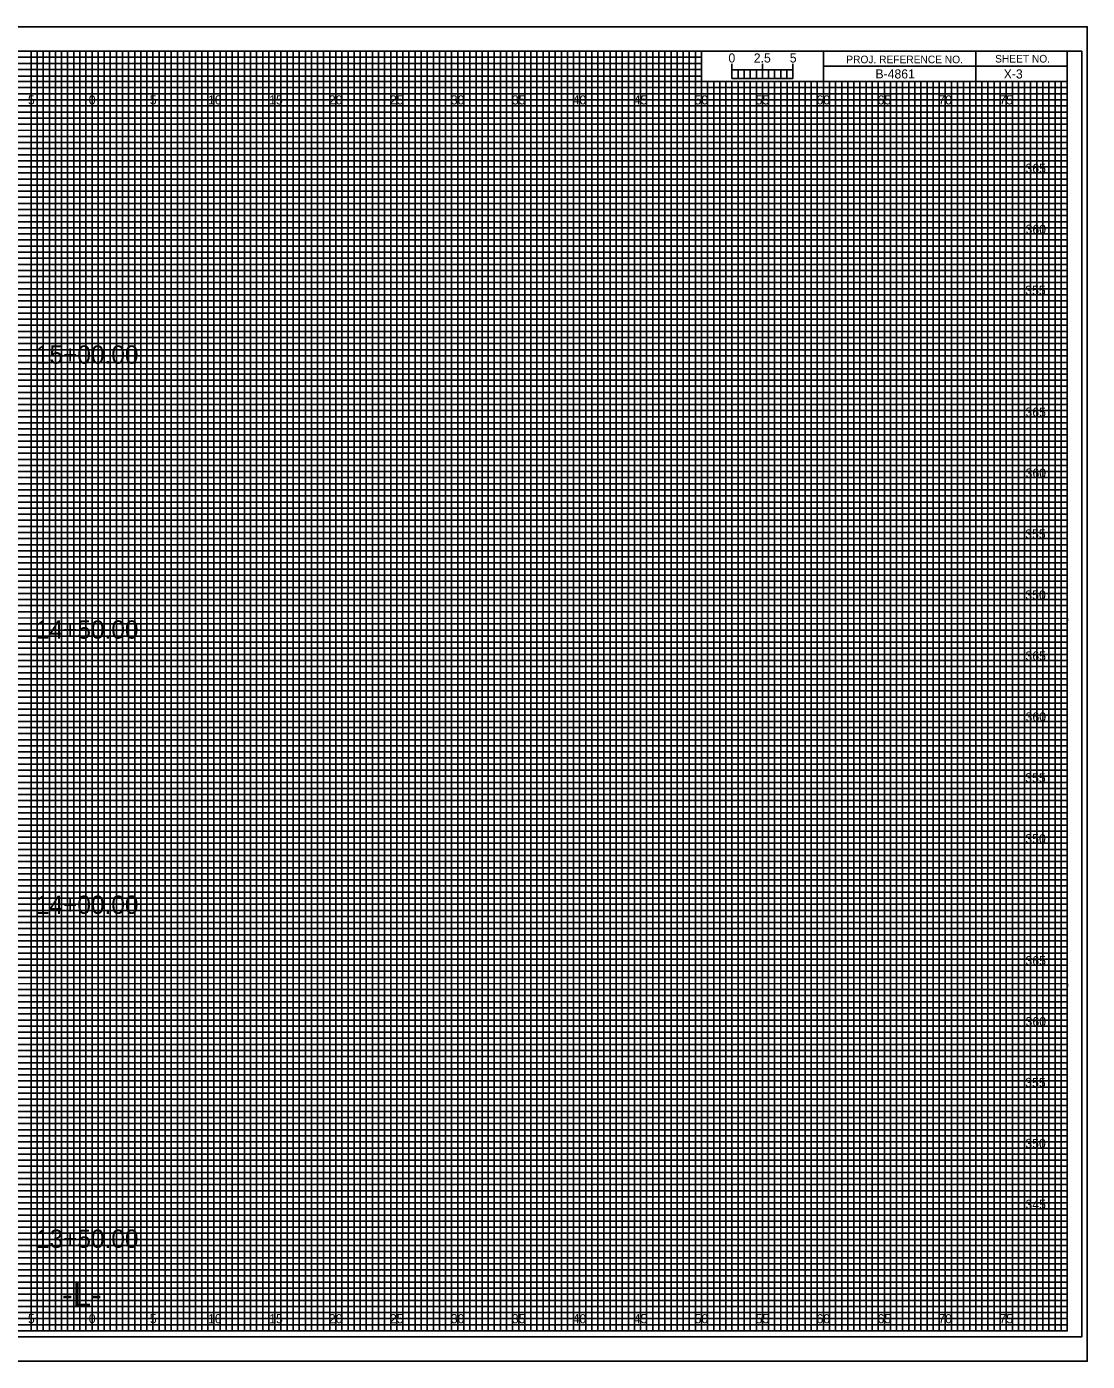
# Model space of a CAD drawing. Extents: x -7 to 266, y -5 to 437.
# Drawn here: x 74.6 to 161.7, y 217.5 to 327 of the extents above; entities that cross this region are included whole.
import ezdxf

# ---------------------------------------------------------------- set-up
doc = ezdxf.new("R2010")
doc.units = 0
for name, color, linetype in [('Exist XS Center Line Elevation Label', 7, 'Continuous'), ('Exist XS Ground Line', 7, 'Continuous'), ('Prop XS Dump Level', 7, 'Continuous'), ('Prop XS EOT Tick Mark', 7, 'Continuous'), ('Prop XS Finish Grade', 7, 'Continuous'), ('Prop XS Finish Grade Concrete', 7, 'Continuous'), ('Prop XS Finish Grade Earthwork', 7, 'Continuous'), ('Prop XS Finish Grade Pavement', 7, 'Continuous'), ('Prop XS Geopak Shape', 7, 'Continuous'), ('Prop XS Hydro Elevations', 7, 'Continuous'), ('Prop XS Pvmt Edge Slope', 7, 'Continuous'), ('Prop XS SE Text', 7, 'Continuous'), ('Prop XS Side Slope Text', 7, 'Continuous'), ('Prop XS SS Elevation Text', 7, 'Continuous'), ('Prop XS Subgrade Earthwork', 7, 'Continuous'), ('Prop XSC Text', 7, 'Continuous'), ('Typical Guardrail CELL', 7, 'Continuous')]:
    doc.layers.add(name, color=color, linetype=linetype)

msp = doc.modelspace()

# ---------------------------------------------------------------- linework, layer by layer
at = {"layer": 'Exist XS Center Line Elevation Label'}
for points in [[(72.5, 220), (77.5, 220), (77.5, 325), (82.5, 325), (82.5, 220), (87.5, 220), (87.5, 325), (92.5, 325), (92.5, 220), (97.5, 220), (97.5, 325), (102.5, 325), (102.5, 220), (107.5, 220), (107.5, 325), (112.5, 325), (112.5, 220), (117.5, 220), (117.5, 325), (122.5, 325), (122.5, 220), (127.5, 220), (127.5, 325), (129.97, 325), (130, 325), (130, 322.5), (132.5, 322.5), (132.5, 220), (137.5, 220), (137.5, 322.5), (142.5, 322.5), (142.5, 220), (147.5, 220), (147.5, 322.5), (152.5, 322.5), (152.5, 220), (157.5, 220), (157.5, 322.5)], [(0, 322.5), (137.5, 322.5)], [(0, 312.5), (160, 312.5), (160, 317.5), (0, 317.5)], [(0, 302.5), (160, 302.5), (160, 307.5), (0, 307.5)], [(0, 292.5), (160, 292.5), (160, 297.5), (0, 297.5)], [(0, 282.5), (160, 282.5), (160, 287.5), (0, 287.5)], [(0, 272.5), (160, 272.5), (160, 277.5), (0, 277.5)], [(0, 262.5), (160, 262.5), (160, 267.5), (0, 267.5)], [(0, 252.5), (160, 252.5), (160, 257.5), (0, 257.5)], [(0, 242.5), (160, 242.5), (160, 247.5), (0, 247.5)], [(0, 232.5), (160, 232.5), (160, 237.5), (0, 237.5)], [(0, 222.5), (160, 222.5), (160, 227.5), (0, 227.5)]]:
    msp.add_lwpolyline(points, dxfattribs=at)
at = {"layer": 'Exist XS Ground Line'}
for p, q in [((75, 325), (70, 325)), ((75, 220), (75, 325)), ((85, 325), (80, 325)), ((80, 325), (80, 220)), ((85, 220), (85, 325)), ((95, 325), (90, 325)), ((90, 325), (90, 220)), ((95, 220), (95, 325)), ((105, 325), (100, 325)), ((100, 325), (100, 220)), ((105, 220), (105, 325)), ((115, 325), (110, 325)), ((110, 325), (110, 220)), ((115, 220), (115, 325)), ((125, 325), (120, 325)), ((120, 325), (120, 220)), ((125, 220), (125, 325)), ((130, 325), (130, 220)), ((135, 220), (135, 322.5)), ((145, 322.5), (140, 322.5)), ((140, 322.5), (140, 220)), ((145, 220), (145, 322.5)), ((155, 322.5), (150, 322.5)), ((150, 322.5), (150, 220)), ((155, 220), (155, 322.5)), ((80, 220), (75, 220)), ((90, 220), (85, 220)), ((100, 220), (95, 220)), ((110, 220), (105, 220)), ((120, 220), (115, 220)), ((130, 220), (125, 220)), ((140, 220), (135, 220)), ((150, 220), (145, 220)), ((160, 220), (155, 220)), ((160, 220), (160, 220))]:
    msp.add_line(p, q, dxfattribs=at)
for points in [[(0, 320), (160, 320), (160, 315), (0, 315)], [(0, 310), (160, 310), (160, 305), (0, 305)], [(0, 300), (160, 300), (160, 295), (0, 295)], [(0, 290), (160, 290), (160, 285), (0, 285)], [(0, 280), (160, 280), (160, 275), (0, 275)], [(0, 270), (160, 270), (160, 265), (0, 265)], [(0, 260), (160, 260), (160, 255), (0, 255)], [(0, 250), (160, 250), (160, 245), (0, 245)], [(0, 240), (160, 240), (160, 235), (0, 235)], [(0, 230), (160, 230), (160, 225), (0, 225)]]:
    msp.add_lwpolyline(points, dxfattribs=at)
at = {"layer": 'Prop XS Finish Grade'}
for p, q in [((75, 220), (75, 325)), ((80, 220), (80, 325)), ((85, 220), (85, 325)), ((90, 220), (90, 325)), ((95, 220), (95, 325)), ((100, 220), (100, 325)), ((105, 220), (105, 325)), ((110, 220), (110, 325)), ((115, 220), (115, 325)), ((120, 220), (120, 325)), ((125, 220), (125, 325)), ((130, 220), (130, 322.34)), ((135, 220), (135, 322.34)), ((140, 220), (140, 322.34)), ((145, 220), (145, 322.34)), ((150, 220), (150, 322.34)), ((155, 220), (155, 322.34)), ((0, 320), (160, 320)), ((0, 315), (160, 315)), ((0, 310), (160, 310)), ((0, 305), (160, 305)), ((0, 300), (160, 300)), ((0, 295), (160, 295)), ((0, 290), (160, 290)), ((0, 285), (160, 285)), ((0, 280), (160, 280)), ((0, 275), (160, 275)), ((0, 270), (160, 270)), ((0, 265), (160, 265)), ((0, 260), (160, 260)), ((0, 255), (160, 255)), ((0, 250), (160, 250)), ((0, 245), (160, 245)), ((0, 240), (160, 240)), ((0, 235), (160, 235)), ((0, 230), (160, 230)), ((0, 225), (160, 225))]:
    msp.add_line(p, q, dxfattribs=at)
at = {"layer": 'Prop XS Finish Grade Earthwork'}
msp.add_lwpolyline([(-6.7, 217.5), (161.65, 217.5), (161.65, 327), (-6.7, 327)], close=True, dxfattribs=at)
at = {"layer": 'Prop XS Hydro Elevations'}
for p, q in [((152.5, 325), (152.5, 322.5)), ((152.5, 322.5), (152.5, 325)), ((160, 323.75), (140, 323.75)), ((140, 323.75), (140, 322.5)), ((140, 322.5), (160, 322.5))]:
    msp.add_line(p, q, dxfattribs=at)
for points in [[(160, 325), (0, 325), (0, 220), (160, 220)], [(140, 325), (130, 325), (130, 322.51), (140, 322.51)], [(160, 325), (140, 325), (140, 322.5), (160, 322.5)]]:
    msp.add_lwpolyline(points, close=True, dxfattribs=at)
at = {"layer": 'Prop XS Pvmt Edge Slope'}
msp.add_lwpolyline([(-5.4, 219.5), (161.2, 219.5), (161.2, 325), (-5.4, 325)], close=True, dxfattribs=at)
at = {"layer": 'Prop XS SE Text'}
for p, q in [((0, 324.5), (130, 324.5)), ((130, 324.5), (130, 323.99)), ((130, 323.99), (0, 323.99)), ((0, 323.5), (130, 323.5)), ((130, 323.5), (130, 322.94)), ((130, 322.94), (0, 322.94)), ((0, 322), (160, 322))]:
    msp.add_line(p, q, dxfattribs=at)
for points in [[(0, 321.5), (135, 321.5), (160, 321.5), (160, 321), (0, 321)], [(0, 320.5), (160, 320.5), (160, 319.5), (0, 319.5)], [(0, 319), (160, 319), (160, 318.5), (0, 318.49)], [(0, 318), (160, 318), (160, 317), (0, 317)], [(0, 316.5), (160, 316.5), (160, 316), (0, 316)], [(0, 315.5), (160, 315.5), (160, 314.5), (0, 314.5)], [(0, 314), (160, 314), (160, 313.5), (0, 313.5)], [(0, 313), (160, 313), (160, 312), (0, 312)], [(0, 311.5), (160, 311.5), (160, 311), (0, 311)], [(0, 310.5), (160, 310.5), (160, 309.5), (0, 309.5)], [(0, 309), (160, 309), (160, 308.5), (0, 308.5)], [(0, 308), (160, 308), (160, 306.98), (160, 306.5), (160, 306), (0, 306)], [(0, 307), (160, 307), (160, 306.5), (0, 306.5)], [(0, 305.5), (160, 305.5), (160, 304.5), (0, 304.51)], [(0, 304.51), (160, 304.5), (160, 304), (0, 304)], [(0, 303.5), (160, 303.5), (160, 303), (0, 303)], [(0, 302), (160, 302), (160, 301.5), (0, 301.5)], [(0, 301), (160, 301), (160, 300.5), (0, 300.5)], [(-0.04, 299.44), (160, 299.44), (160, 298.94), (-0.04, 298.94)], [(0, 298.5), (160, 298.5), (160, 298), (0, 298)], [(0, 297), (160, 297), (160, 296.5), (0, 296.5)], [(0, 296), (160, 296), (160, 295.5), (0, 295.5)], [(0, 294.5), (160, 294.5), (160, 294), (0, 294)], [(0, 293.5), (160, 293.5), (160, 293), (0, 293)], [(0, 292), (160, 292), (160, 291.5), (0, 291.5)], [(0, 291), (160, 291), (160, 290.5), (0, 290.5)], [(0, 289.5), (160, 289.5), (160, 288.99), (0, 289)], [(0, 288.5), (160, 288.5), (160, 288), (0, 288)], [(0, 287), (160, 287), (160, 286.5), (0, 286.5)], [(0, 286), (160, 286), (160, 285.5), (0, 285.5)], [(0, 284.5), (160, 284.5), (160, 284), (0, 284)], [(0, 283.5), (160, 283.5), (160, 283), (0, 283)], [(0, 282), (160, 282), (160, 281.5), (0, 281.5)], [(0, 281), (160, 281), (160, 280.5), (0, 280.5)], [(0, 279.5), (160, 279.5), (160, 279), (0, 279)], [(0, 278.5), (160.03, 278.45), (160, 278), (0, 278)], [(0, 277), (160, 277), (160, 276.5), (0, 276.5)], [(0, 276), (160, 276), (160, 275.5), (0, 275.5)], [(0, 274.5), (160, 274.5), (160, 274), (0, 274)], [(0, 273.5), (160, 273.5), (160, 273), (0, 273)], [(0, 272), (160, 272), (160, 271.5), (0, 271.5)], [(0, 271), (160, 271), (160, 270.5), (0, 270.5)], [(0, 269.5), (160, 269.5), (160, 269), (0, 269)], [(0, 268.5), (160, 268.5), (160, 268), (0, 268)], [(0, 267), (160, 267), (160, 266.5), (0, 266.5)], [(0, 266), (160, 266), (160, 265.5), (0, 265.5)], [(0, 264.5), (160, 264.5), (160, 264), (0, 264)], [(0, 263.5), (160, 263.5), (160, 263), (0, 263)], [(0, 262), (160, 262), (160, 261.5), (0, 261.5)], [(0, 261), (160, 261), (160, 260.5), (0, 260.5)], [(0, 259.5), (160, 259.5), (160, 258.99), (0, 259)], [(0, 258.5), (160, 258.5), (160, 258), (0, 258)], [(0, 257), (160, 257), (160, 256.5), (0, 256.5)], [(0, 256), (160, 256), (160, 255.5), (0, 255.5)], [(0, 254.5), (160, 254.5), (160, 254), (0, 254)], [(0, 253.5), (160, 253.5), (160, 253), (0, 253)], [(0, 252), (160, 252), (160, 251.5), (0, 251.5)], [(0, 251), (160, 251), (160, 250.5), (0, 250.5)], [(0, 249.5), (160, 249.5), (160, 249), (0, 249)], [(0, 248.5), (160.03, 248.46), (160, 248), (0, 248)], [(0, 247), (160, 247), (160, 246.5), (0, 246.5)], [(0, 246), (160, 246), (160, 245.5), (0, 245.5)], [(0, 244.5), (160, 244.5), (160, 244), (0, 244)], [(0, 243.5), (160, 243.5), (160, 243), (0, 243)], [(0, 242), (160, 242), (160, 241.5), (0, 241.5)], [(0, 241), (160, 241), (160, 240.5), (0, 240.5)], [(0, 239.5), (160, 239.5), (160, 239), (0, 239)], [(0, 238.5), (160, 238.5), (160, 238), (0, 238)], [(0, 237), (160, 237), (160, 236.5), (0, 236.5)], [(0, 236), (160, 236), (160, 235.5), (0, 235.5)], [(0, 234.5), (160, 234.5), (160, 234), (0, 234)], [(0, 233.5), (160, 233.5), (160, 233), (0, 233)], [(0, 232), (160, 232), (160, 231.5), (0, 231.5)], [(0, 231), (160, 231), (160, 230.5), (0, 230.5)], [(0, 229.5), (160, 229.5), (160, 229), (0, 229)], [(0, 228.5), (160, 228.5), (160, 228), (0, 228)], [(0, 227), (160, 227), (160, 226.5), (0, 226.5)], [(0, 226), (160, 226), (160, 225.5), (0, 225.5)], [(0, 224.5), (160, 224.5), (160, 224), (0, 224)], [(0, 223.5), (160, 223.5), (160, 223), (0, 223)], [(0, 222), (160, 222), (160, 221.5), (0, 221.5)], [(0, 221), (160, 221), (160, 220.5), (0, 220.5)]]:
    msp.add_lwpolyline(points, dxfattribs=at)
at = {"layer": 'Prop XS Side Slope Text'}
for p, q in [((132.5, 322.75), (132.5, 323.95)), ((132.5, 323.45), (132.5, 323.95)), ((135, 322.75), (135, 323.95)), ((137.5, 322.75), (137.5, 323.95)), ((137.5, 323.45), (137.5, 323.95))]:
    msp.add_line(p, q, dxfattribs=at)
for points in [[(137.5, 323.45), (132.5, 323.45), (132.5, 322.75), (137.5, 322.75)], [(132.5, 323.45), (133, 323.45), (133, 322.75), (132.5, 322.75)], [(133.5, 323.45), (134, 323.45), (134, 322.75), (133.5, 322.75)], [(134.5, 323.45), (135, 323.45), (135, 322.75), (134.5, 322.75)], [(135.5, 323.45), (136, 323.45), (136, 322.75), (135.5, 322.75)], [(136.5, 323.45), (137, 323.45), (137, 322.75), (136.5, 322.75)]]:
    msp.add_lwpolyline(points, close=True, dxfattribs=at)
at = {"layer": 'Prop XS SS Elevation Text'}
for p, q in [((133.5, 322.5), (133, 322.5)), ((133, 322.5), (133, 220)), ((133.5, 220), (133.5, 322.5)), ((134.5, 322.5), (134, 322.5)), ((134, 322.5), (134, 220)), ((134.5, 220), (134.5, 322.5)), ((133, 220), (132.5, 220)), ((134, 220), (133.5, 220))]:
    msp.add_line(p, q, dxfattribs=at)
for points in [[(75, 220), (75.5, 220), (75.5, 325), (76, 325), (76, 220)], [(76, 220), (76.5, 220), (76.5, 325), (77, 325), (77, 220)], [(77.5, 220), (78, 220), (78, 325), (78.5, 325), (78.5, 220)], [(78.5, 220), (79, 220), (79, 325), (79.5, 325), (79.5, 220)], [(80, 220), (80.5, 220), (80.5, 325), (81, 325), (81, 220)], [(81, 220), (81.5, 220), (81.5, 325), (82, 325), (82, 220)], [(82.5, 220), (83, 220), (83, 325), (83.5, 325), (83.5, 220)], [(83.5, 220), (84, 220), (84, 325), (84.5, 325), (84.5, 220)], [(85, 220), (85.5, 220), (85.5, 325), (86, 325), (86, 220)], [(86, 220), (86.5, 220), (86.5, 325), (87, 325), (87, 220)], [(87.5, 220), (88, 220), (88, 325), (88.5, 325), (88.5, 220)], [(88.5, 220), (89, 220), (89, 325), (89.5, 325), (89.5, 220)], [(90, 220), (90.5, 220), (90.5, 325), (91, 325), (91, 220)], [(91, 220), (91.5, 220), (91.5, 325), (92, 325), (92, 220)], [(92.5, 220), (93, 220), (93, 325), (93.5, 325), (93.5, 220)], [(93.5, 220), (94, 220), (94, 325), (94.5, 325), (94.5, 220)], [(95, 220), (95.5, 220), (95.5, 325), (96, 325), (96, 220)], [(96, 220), (96.5, 220), (96.5, 325), (97, 325), (97, 220)], [(97.5, 220), (98, 220), (98, 325), (98.5, 325), (98.5, 220)], [(98.5, 220), (99, 220), (99, 325), (99.5, 325), (99.5, 220)], [(100, 220), (100.5, 220), (100.5, 325), (101, 325), (101, 220)], [(101, 220), (101.5, 220), (101.5, 325), (102, 325), (102, 220)], [(102.5, 220), (103, 220), (103, 325), (103.5, 325), (103.5, 220)], [(103.5, 220), (104, 220), (104, 325), (104.5, 325), (104.5, 220)], [(105, 220), (105.5, 220), (105.5, 325), (106, 325), (106, 220)], [(106, 220), (106.5, 220), (106.5, 325), (107, 325), (107, 220)], [(107.5, 220), (108, 220), (108, 325), (108.5, 325), (108.5, 220)], [(108.5, 220), (109, 220), (109, 325), (109.5, 325), (109.5, 220)], [(110, 220), (110.5, 220), (110.5, 325), (111, 325), (111, 220)], [(111, 220), (111.5, 220), (111.5, 325), (112, 325), (112, 220)], [(112.5, 220), (113, 220), (113, 325), (113.5, 325), (113.5, 220)], [(113.5, 220), (114, 220), (114, 325), (114.5, 325), (114.5, 220)], [(115, 220), (115.5, 220), (115.5, 325), (116, 325), (116, 220)], [(116, 220), (116.5, 220), (116.5, 325), (117, 325), (117, 220)], [(117.5, 220), (118, 220), (118, 325), (118.5, 325), (118.5, 220)], [(118.5, 220), (119, 220), (119, 325), (119.5, 325), (119.5, 220)], [(120, 220), (120.5, 220), (120.5, 325), (121, 325), (121, 220)], [(121, 220), (121.5, 220), (121.5, 325), (122, 325), (122, 220)], [(122.5, 220), (123, 220), (123, 325), (123.5, 325), (123.5, 220)], [(123.5, 220), (124, 220), (124, 325), (124.5, 325), (124.5, 220)], [(125, 220), (125.5, 220), (125.5, 325), (126, 325), (126, 220)], [(126, 220), (126.5, 220), (126.5, 325), (127, 325), (127, 220)], [(127.5, 220), (128, 220), (128, 325), (128.5, 325), (128.5, 220)], [(128.5, 220), (129, 220), (129, 325), (129.5, 325), (129.5, 220)], [(130, 220), (130.5, 220), (130.5, 322.5), (131.01, 322.5), (131.01, 220)], [(131, 220), (131.5, 220), (131.5, 322.5), (132, 322.5), (132, 220)], [(135, 220), (135.49, 220), (135.49, 322.5), (136, 322.5), (136, 220)], [(136, 220), (136.5, 220), (136.5, 322.5), (137.03, 322.5), (137.03, 220)], [(137.5, 220), (138, 220), (138, 322.5), (138.5, 322.5), (138.5, 220)], [(138.5, 220), (139, 220), (139, 322.5), (139.5, 322.5), (139.5, 220)], [(140, 220), (140.5, 220), (140.5, 322.5), (141, 322.5), (141, 220)], [(141, 220), (141.5, 220), (141.5, 322.5), (142, 322.5), (142, 220)], [(142.5, 220), (143, 220), (143, 322.5), (143.5, 322.5), (143.5, 220)], [(143.5, 220), (144, 220), (144, 322.5), (144.5, 322.5), (144.5, 220)], [(145, 220), (145.5, 220), (145.5, 322.5), (146, 322.5), (146, 220)], [(146, 220), (146.5, 220), (146.5, 322.5), (147, 322.5), (147, 220)], [(147.5, 220), (148, 220), (148, 322.5), (148.5, 322.5), (148.5, 220)], [(148.5, 220), (149, 220), (149, 322.5), (149.5, 322.5), (149.5, 220)], [(150, 220), (150.5, 220), (150.5, 322.5), (151, 322.5), (151, 220)], [(151, 220), (151.5, 220), (151.5, 322.5), (152, 322.5), (152, 220)], [(152.5, 220), (153, 220), (153, 322.5), (153.5, 322.5), (153.5, 220)], [(153.5, 220), (154, 220), (154, 322.5), (154.5, 322.5), (154.5, 220)], [(155, 220), (155.5, 220), (155.5, 322.5), (156, 322.5), (156, 220)], [(156, 220), (156.5, 220), (156.5, 322.5), (157, 322.5), (157, 220)], [(157.5, 220), (158, 220), (158, 322.5), (158.5, 322.5), (158.5, 220)], [(158.5, 220), (159, 220), (159, 322.5), (159.5, 322.5), (159.5, 220)]]:
    msp.add_lwpolyline(points, dxfattribs=at)
at = {"layer": 'Prop XS Subgrade Earthwork'}
for p, q in [((161.65, 327), (-6.7, 327)), ((-6.7, 217.5), (161.65, 217.5))]:
    msp.add_line(p, q, dxfattribs=at)

# ---------------------------------------------------------------- texts
at = {"layer": 'Prop XS Dump Level'}
msp.add_text('-L-', height=2, dxfattribs=at).set_placement((77.53, 222))
at = {"layer": 'Prop XS EOT Tick Mark'}
msp.add_text('X-3', height=0.75, dxfattribs=at).set_placement((154.79, 322.75))
at = {"layer": 'Prop XS Finish Grade Concrete'}
for s, p in [('365', (156.58, 315)), ('360', (156.59, 310)), ('355', (156.56, 305)), ('365', (156.58, 295)), ('360', (156.59, 290)), ('355', (156.56, 285)), ('350', (156.57, 280)), ('365', (156.58, 275)), ('360', (156.59, 270)), ('355', (156.56, 265)), ('350', (156.57, 260)), ('365', (156.58, 250)), ('360', (156.59, 245)), ('355', (156.56, 240)), ('350', (156.57, 235)), ('345', (156.58, 230))]:
    msp.add_text(s, height=0.75, dxfattribs=at).set_placement(p)
at = {"layer": 'Prop XS Finish Grade Pavement'}
msp.add_text('B-4861', height=0.75, dxfattribs=at).set_placement((144.27, 322.75))
at = {"layer": 'Prop XS Geopak Shape'}
for s, p in [('2.5', (134.29, 324.06)), ('5', (137.24, 324.06))]:
    msp.add_text(s, height=0.75, dxfattribs=at).set_placement(p)
at = {"layer": 'Prop XS Hydro Elevations'}
for s, p in [('PROJ. REFERENCE NO.', (141.88, 324)), ('SHEET NO.', (154.09, 324.06))]:
    msp.add_text(s, height=0.625, dxfattribs=at).set_placement(p)
at = {"layer": 'Prop XS Side Slope Text'}
msp.add_text('0', height=0.75, dxfattribs=at).set_placement((132.21, 324.06))
at = {"layer": 'Prop XSC Text'}
for s, p in [('15+00.00', (75.39, 299.35)), ('14+50.00', (75.39, 276.79)), ('14+00.00', (75.39, 254.21)), ('13+50.00', (75.39, 226.81))]:
    msp.add_text(s, height=1.5, dxfattribs=at).set_placement(p)
at = {"layer": 'Typical Guardrail CELL'}
for s, p in [('5', (74.74, 320.62)), ('0', (79.73, 320.62)), ('0', (79.73, 320.62)), ('5', (84.74, 320.62)), ('10', (89.52, 320.62)), ('15', (94.53, 320.62)), ('20', (99.43, 320.62)), ('25', (104.44, 320.62)), ('30', (109.43, 320.62)), ('35', (114.44, 320.62)), ('40', (119.43, 320.62)), ('45', (124.44, 320.62)), ('50', (129.43, 320.62)), ('55', (134.44, 320.62)), ('60', (139.43, 320.62)), ('65', (144.44, 320.62)), ('70', (149.43, 320.62)), ('75', (154.44, 320.62)), ('5', (74.74, 220.62)), ('0', (79.73, 220.62)), ('0', (79.73, 220.62)), ('5', (84.74, 220.62)), ('10', (89.52, 220.62)), ('15', (94.53, 220.62)), ('20', (99.43, 220.62)), ('25', (104.44, 220.62)), ('30', (109.43, 220.62)), ('35', (114.44, 220.62)), ('40', (119.43, 220.62)), ('45', (124.44, 220.62)), ('50', (129.43, 220.62)), ('55', (134.44, 220.62)), ('60', (139.43, 220.62)), ('65', (144.44, 220.62)), ('70', (149.43, 220.62)), ('75', (154.44, 220.62))]:
    msp.add_text(s, height=0.75, dxfattribs=at).set_placement(p)

doc.saveas('drawing.dxf')
